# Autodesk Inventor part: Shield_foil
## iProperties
Shininess: 64.0
Length Units: 11269
Angle Units: 11279
Time Units: 11290
Mass Units: 11283
Length Display Precision: 3
Angle Display Precision: 2
Compacted: True
Part Number: Shield_foil
Document SubType Name: Modeling
Created: 2003-02
Material: Standard
Designer: hofer_a
Density: 0.0
Volumn: 0.0
Area: 0.0
PropertySet Name: Model Information
Control State: 0
Master: False
Checked Out: False
Author: hofer_a
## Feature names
1. Extrusion1
